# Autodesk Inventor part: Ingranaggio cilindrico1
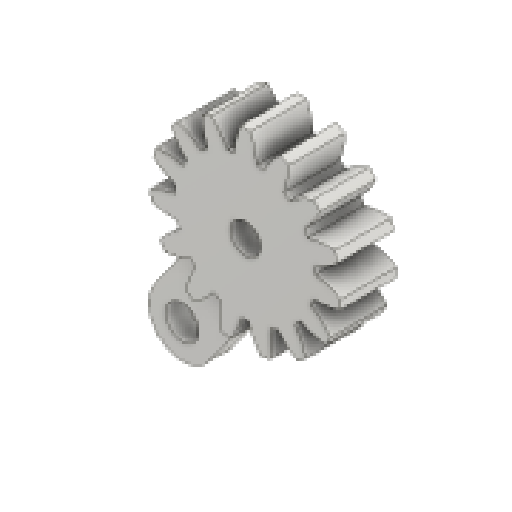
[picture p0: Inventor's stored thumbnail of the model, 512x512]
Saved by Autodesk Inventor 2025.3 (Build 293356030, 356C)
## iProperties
CustomPartVersion: 1
Created: 2026-03
Part Number: Ingranaggio cilindrico1
Material: Steel
Document SubType Name: Modeling
Designer: R5800u
Categories: <?xml version="1.0" encoding="UTF-16"?> <MemberInstance><Categories><FamilyTemplate><FamilyTemplateParameter ValueType="xs:double" Id="1" ObjectReferenceKey="da
Density: 1 g/cm^3
Appearance: Steel
Author: R5800u
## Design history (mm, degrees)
sketch "Sketch1"
  geometry: C1 r 8.5 at (0, 0)
  constraints: 1 centre point
  dimensions: "d0" = 17 diameter of C1 (= da_da)
extrude "Extrusion1" new body sketch "Sketch1" distance "d1" = 5 (= da_b); taper "d2" = 0 deg
workplane "Work Plane2"
feature "Diametro primitivo" dims "d4" = 10, "d5" = 0
workplane "Work Plane8"
workplane "Work Plane9"
feature "Ingranaggio cilindrico" dims "da_b" = 5, "da_d" = 15, "da_aw" = 15, "da_da" = 17, "da_df" = 12.5, "da_dw" = 15, angle "da_beta" = 0 deg, "da_lefttooth" = 0, "da_righttooth" = 0
sketch "Schizzo3"
  geometry: A1 r 6.25 centre (0, 0) between (5.835, -2.24) and (6.037, -1.618) reference; 2 further points
  constraints: 1 coincident
hole "Foro1" sketch "Schizzo3" at (0, 0) diameter "d49" = 2.7; stored, may be unused: countersink angle "d53" = 90 deg, drill point angle "d55" = 118 deg; dims "d50" = 6, "d51" = 4.5, "d52" = 2, "d54" = 8
sketch "Schizzo4"
  geometry: L1 (25.195, -9.923)-(31.073, -6.121) reference; L2 (31.073, -6.121)-(28.357, -1.922) reference; L3 (28.357, -1.922)-(22.48, -5.724) reference; L4 (21.492, -6.959)-(11.416, -13.476) reference; L5 (13.589, -16.835)-(23.664, -10.317) reference; L6 (0, 0)-(11.243, -15.97); L7 (-2.95, -1.02)-(8.79, -17.697); L8 (1.956, 2.433)-(13.696, -14.243); C1 r 1.6 at (11.243, -15.97) reference; C2 r 1.6 at (23.838, -7.823) reference; C3 r 1.35 at (0, 0) reference; C4 r 2.25 at (0, 0) reference; C5 r 3 at (8.635, -12.265); C6 r 1.5 at (8.635, -12.265); A1 r 2.5 centre (23.838, -7.823) between (23.664, -10.317) and (25.195, -9.923) reference; A2 r 2.5 centre (23.838, -7.823) between (22.48, -5.724) and (21.492, -6.959) reference; A3 r 2.5 centre (11.243, -15.97) between (11.416, -13.476) and (13.589, -16.835) reference; A4 r 6.25 centre (0, 0) between (4.419, -4.419) and (4.857, -3.933) reference; 11 further points
  constraints: 6 end point, 2 centre point, 2 coincident, 2 parallel, 1 point on line, 1 tangent, 3 other
  dimensions: "d56" = 3 distance between parallel lines of L6 L7; "d57" = 3 distance between parallel lines of L6 L8; "d61" = 15 distance of point (0, 0) C5.centre; "d62" = 3 diameter of C6
  node "Riferimento1"
node "Piano di lavoro11"
extrude "Estrusione2" join sketch "Schizzo4" stored distance "d58" = 10; taper "d59" = 0 deg
body "Solid1"
sketch "Sketch2"
  geometry: C1 r 8.5 at (0, 0) reference; C2 r 7.5 at (0, 0)
  constraints: 1 centre point, 1 coincident
  dimensions: "d3" = 15 diameter of C2 (= da_d)
body "Srf1"
other parameters: "d16" = 15 (= da_aw), "d17" = 0, "d34" = 12 deg (computed from da_z), "d39" = 0, "d41" = 0, "d43" = 15 (= da_aw), "d46" = 15 (= da_aw), "d47" = 0, "d48" = 0
